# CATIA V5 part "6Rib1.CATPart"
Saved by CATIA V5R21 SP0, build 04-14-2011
Part number: Rib1
Bounding box of the stored display mesh (mm): x 12 to 22, y -42.784 to 24.466, z 44.2 to 68.578
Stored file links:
  F:\教程\Robotic_Arm_Arduino_Kinect\机械臂CAD\Arm_Detailed_Design\Rib1.CATPart
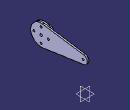
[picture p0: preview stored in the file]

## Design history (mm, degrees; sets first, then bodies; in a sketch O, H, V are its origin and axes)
Body1 (main body)
  DatumSurface1
  DatumSurface2
  Plane1 to Plane3: stored without definition
  Sketch1 on face of DatumSurface1, origin (22, 0, 0), H (0, 1, 0), V (0, 0, 1)
    projected circle E1 centre (-30.534, 56.389) radius 12.25 from edge of DatumSurface2
    projected arc E2 centre (-30.534, 56.389) radius 12.25 from (-28.7577, 68.5095) to (-28.7577, 44.2684) ccw from edge of DatumSurface2
    projected circle E3 centre (-30.534, 56.389) radius 1.5 from edge of DatumSurface2
    arc A1 centre (19.466, 56.389) radius 5 from (20.191, 51.4418) to (20.191, 61.3361) ccw
    point P1 (19.466, 56.389)
    reference intersected line E4 through (-30.534, 0) direction (0, 1) from Plane1
    line L1 (20.191, 61.3361) -> (-28.7577, 68.5095)
    axis line L2 (30.2795, 56.389) -> (-56.8378, 56.389)
    reference intersected line E5 through (0, 56.389) direction (1, 0) from Plane2
    line L3 (-28.7577, 44.2684) -> (20.191, 51.4418)
    point P4 (-28.7577, 44.2684)
    point P5 (-28.7577, 68.5095)
    point P8 (-28.7577, 68.5095)
    circle A2 centre (19.466, 56.389) radius 1.25
    circle A3 centre (-30.534, 64.889) radius 1.25
    point P9 (-30.534, 64.889)
    reference intersected line E6 through (0, 56.389) direction (-1, 0) from Plane3
    circle A4 centre (-39.034, 56.389) radius 1.25
    circle A5 centre (-30.534, 47.889) radius 1.25
    circle A6 centre (-22.034, 56.389) radius 1.25
    distance P1 E4 = 50
    radius A1 = 5
    radius A2 = 1.25
    radius A3 = 1.25
    distance E6 P9 = 8.5
    tangency: L1 E1, L1 A1, L3 A1, L3 E1
    horizontal: L2 H
    coincidence: P1 L2, L2 E5, E1 P4, E1 P5, L1 P8, P5 P8
  Pad1: profile Sketch1, direction (-1, 0, 0), length 2
Body2
  Sketch2 on end face of Pad1, origin (20, 0, 0), H (0, -1, 0), V (0, 0, 1)
    circle A1 centre (30.534, 56.389) radius 12.25
    point P1 (30.534, 56.389)
    reference projected arc E1 centre (30.534, 56.389) radius 12.25 from (28.7577, 44.2684) to (28.7577, 68.5095) ccw from edge [end face of Pad1 | face of Pad1 from Sketch1.E2]
    circle A2 centre (30.534, 64.889) radius 1.25
    point P2 (30.534, 64.889)
    circle A3 centre (39.034, 56.389) radius 1.25
    point P3 (39.034, 56.389)
    circle A4 centre (30.534, 47.889) radius 1.25
    point P4 (30.534, 47.889)
    circle A5 centre (22.034, 56.389) radius 1.25
    point P5 (22.034, 56.389)
    circle A6 centre (30.534, 56.389) radius 4
    radius A2 = 1.25
    radius A3 = 1.25
    radius A4 = 1.25
    radius A5 = 1.25
    distance P2 P1 = 8.5
    distance P3 P1 = 8.5
    distance P1 P4 = 8.5
    distance P5 P1 = 8.5
    radius A6 = 4
    coincidence: A1 E1
  Pad2: profile Sketch2, direction (-1, 0, 0), length 2
  Sketch3 on end face of Pad2, origin (18, 0, 0), H (0, -1, 0), V (0, 0, 1)
    circle A1 centre (30.534, 56.389) radius 6
    reference projected circle E1 centre (30.534, 56.389) radius 12.25 from edge [face of Pad2 from Sketch2.A1 | end face of Pad2]
    circle A2 centre (30.534, 56.389) radius 4
    radius A1 = 6
    radius A2 = 4
    concentricity: A1 E1
  Pad3: profile Sketch3, direction (-1, 0, 0), length 6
